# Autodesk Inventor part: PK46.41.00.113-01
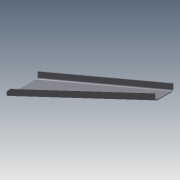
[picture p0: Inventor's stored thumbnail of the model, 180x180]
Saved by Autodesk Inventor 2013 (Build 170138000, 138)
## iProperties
Created: 2005-07
Part Number: PK46.41.00.113-01
Material: Steel, Mild
Document SubType Name: Modeling
Designer: PVitaliy
Manufacturer: Standard
Standards Organization: Custom
Density: 7.86 g/cm^3
Author: PVitaliy
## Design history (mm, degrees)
derived "PK46.41.00.113.ipt"
body "Solid1"
tag "TaggingFeature2"
feature "DerivedBody::PK46.41.00.113.ipt" dims "d3" = 10
